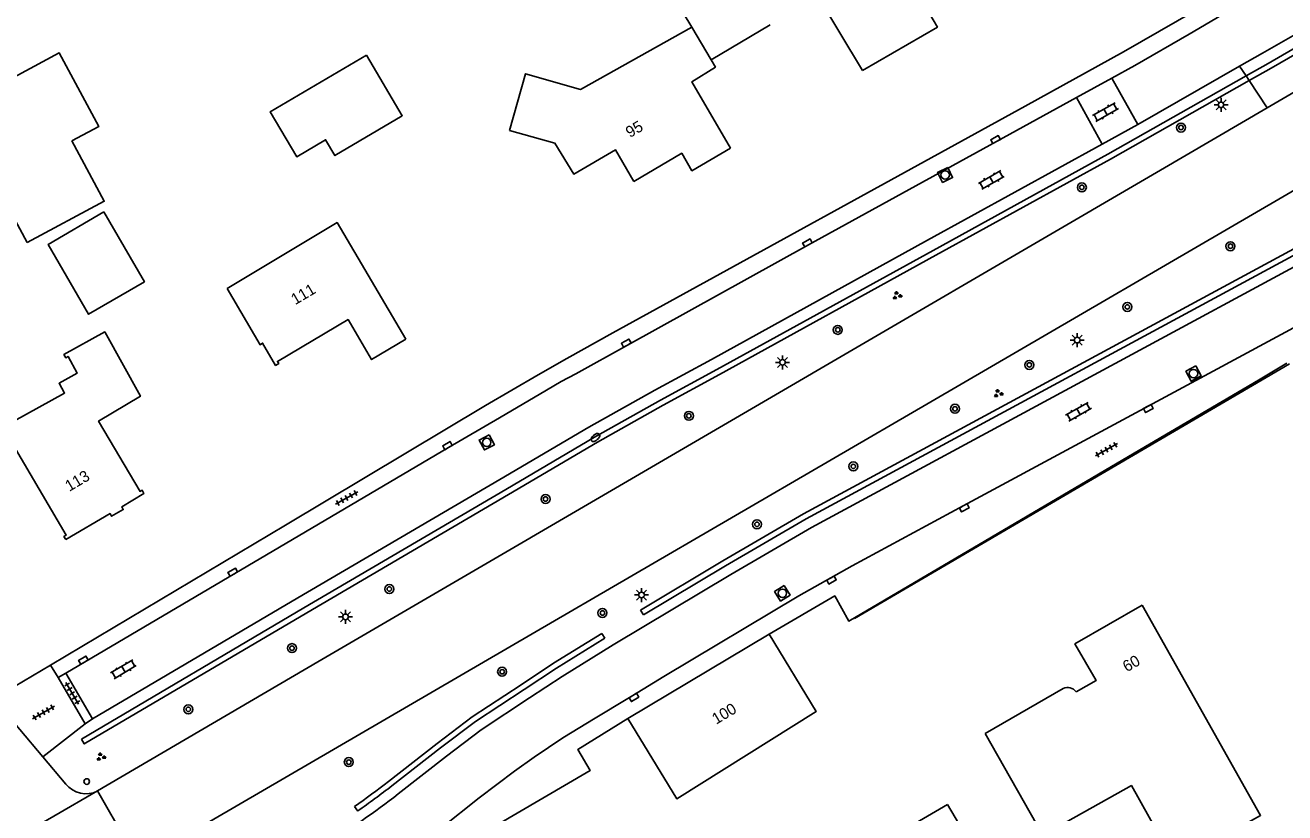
# Model space of a CAD drawing. Extents: x 135999 to 138000, y 396000 to 398501.
# Drawn here: x 136302.3 to 136414.4, y 397566.8 to 397636.9 of the extents above; entities that cross this region are included whole.
import ezdxf

# ---------------------------------------------------------------- set-up
doc = ezdxf.new("R2010")
doc.units = 0
for name, color, linetype in [('gg-afsc-hekwerk', 7, 'Continuous'), ('gg-anno-huisnummerreeks BGT', 7, 'Continuous'), ('gg-bbg-bijgebouw', 7, 'Continuous'), ('gg-bbg-gedigitaliseerde bebouwing', 7, 'Continuous'), ('gg-bbg-gedigitaliseerde bijgebouw', 7, 'Continuous'), ('gg-bbg-hoofdgebouw', 7, 'Continuous'), ('gg-bbg-luifel en loopbrug', 7, 'Continuous'), ('gg-knt-verharding', 7, 'Continuous'), ('gt-grn-groengrens', 7, 'Continuous'), ('gt-grn-weggrens', 7, 'Continuous'), ('gt-symb-boom', 7, 'Continuous'), ('gt-symb-brandkraan', 7, 'Continuous'), ('gt-symb-groenvak', 7, 'Continuous'), ('gt-symb-klinker verharding', 7, 'Continuous'), ('gt-symb-kolk', 7, 'Continuous'), ('gt-symb-lichtmast', 7, 'Continuous'), ('gt-symb-rioolschacht', 7, 'Continuous'), ('gt-symb-tegel verharding', 7, 'Continuous'), ('gt-symb-verkeersregelinstallatiepaal', 7, 'Continuous')]:
    doc.layers.add(name, color=color, linetype=linetype)

# ---------------------------------------------------------------- blocks, each defined once
blk = doc.blocks.new('gt0-BOOM')
at = {"layer": 'gt-symb-boom'}
for radius in [0.4, 0.2]:
    blk.add_circle((0, 0), radius, dxfattribs=at)
blk = doc.blocks.new('gt0-GRVAK')
at = {"layer": 'gt-symb-groenvak'}
for p, q in [((-0.11, 0.19), (-0.23, 0.24)), ((-0.18, 0.15), (0.09, 0.15)), ((-0.09, 0.21), (-0.16, 0.32)), ((-0.05, 0.21), (-0.05, 0.39)), ((0, 0.21), (0.06, 0.32)), ((0.02, 0.19), (0.13, 0.24)), ((0.26, -0.05), (0.2, 0.06)), ((0.3, -0.05), (0.3, 0.13)), ((0.35, -0.05), (0.41, 0.06)), ((-0.24, -0.23), (-0.36, -0.18)), ((-0.32, -0.26), (-0.05, -0.26)), ((-0.23, -0.21), (-0.29, -0.1)), ((-0.18, -0.2), (-0.18, -0.02)), ((-0.14, -0.21), (-0.07, -0.1)), ((-0.12, -0.23), (0, -0.18)), ((0.24, -0.07), (0.12, -0.02)), ((0.17, -0.11), (0.44, -0.11)), ((0.37, -0.07), (0.49, -0.02))]:
    blk.add_line(p, q, dxfattribs=at)
blk = doc.blocks.new('gt0-RS')
at = {"layer": 'gt-symb-rioolschacht'}
blk.add_lwpolyline([(-0.5, -0.5), (0.5, -0.5), (0.5, 0.5), (-0.5, 0.5)], close=True, dxfattribs=at)
blk.add_circle((0, 0), 0.375, dxfattribs=at)
blk = doc.blocks.new('gt0-KL1')
at = {"layer": 'gt-symb-klinker verharding'}
for p, q in [((-1.15, 0.3), (1.15, 0.3)), ((-1, -0.3), (-1, 0.3)), ((-0.5, 0.3), (-0.5, 0.45)), ((0, -0.3), (0, 0.3)), ((0.5, 0.3), (0.5, 0.45)), ((1, -0.3), (1, 0.3)), ((-1.15, -0.3), (1.15, -0.3)), ((-0.5, -0.45), (-0.5, -0.3)), ((0.5, -0.45), (0.5, -0.3))]:
    blk.add_line(p, q, dxfattribs=at)
blk = doc.blocks.new('gt0-KOLK')
at = {"layer": 'gt-symb-kolk'}
blk.add_lwpolyline([(0, 0), (0.38, 0), (0.38, 0.4), (-0.38, 0.4), (-0.38, 0), (0, 0)], dxfattribs=at)
blk = doc.blocks.new('gt0-LMAST')
at = {"layer": 'gt-symb-lichtmast'}
for p, q in [((-0.18, 0.17), (-0.45, 0.44)), ((-0.01, 0.25), (-0.01, 0.62)), ((0.17, 0.17), (0.44, 0.44)), ((-0.26, 0), (-0.63, 0)), ((-0.18, -0.18), (-0.45, -0.45)), ((-0.01, -0.25), (-0.01, -0.63)), ((0.44, -0.45), (0.17, -0.18)), ((0.24, 0), (0.62, 0))]:
    blk.add_line(p, q, dxfattribs=at)
blk.add_circle((-0.01, 0), 0.25, dxfattribs=at)
blk = doc.blocks.new('gt0-TEG1')
at = {"layer": 'gt-symb-tegel verharding'}
for p, q in [((-1.12, 0), (1.13, 0)), ((-0.9, -0.25), (-0.9, 0.25)), ((-0.45, -0.25), (-0.45, 0.25)), ((0, -0.25), (0, 0.25)), ((0.45, -0.25), (0.45, 0.25)), ((0.9, -0.25), (0.9, 0.25))]:
    blk.add_line(p, q, dxfattribs=at)
blk = doc.blocks.new('gt0-BR')
at = {"layer": 'gt-symb-brandkraan'}
for centre, radius, start, end in [((-0.24, 0), 0.206, 107.5669, 252.4331), ((0.6, -2.66), 3, 106.892, 107.5669), ((0, -0.69), 0.938, 73.108, 106.892), ((-0.6, -2.66), 3, 72.4331, 73.108), ((0.24, 0), 0.206, 287.567, 72.4331), ((0.6, 2.66), 3, 252.4331, 253.108), ((0, 0.69), 0.938, 253.108, 286.8921), ((-0.6, 2.66), 3, 286.8921, 287.567)]:
    blk.add_arc(centre, radius, start, end, dxfattribs=at)
blk = doc.blocks.new('gt0-VIPAAL')
at = {"layer": 'gt-symb-verkeersregelinstallatiepaal'}
blk.add_circle((0, 0), 0.25, dxfattribs=at)

msp = doc.modelspace()

# ---------------------------------------------------------------- linework, layer by layer
at = {"layer": 'gg-afsc-hekwerk'}
msp.add_line((136414.81, 397606.76), (136376.12, 397584.09), dxfattribs=at)
at = {"layer": 'gg-bbg-bijgebouw'}
msp.add_lwpolyline([(136293.54, 397628.05), (136297.09, 397621.4), (136299.69, 397622.8), (136302.52, 397617.53)], dxfattribs=at)
at = {"layer": 'gg-bbg-gedigitaliseerde bebouwing'}
msp.add_line((136371.92, 397641.05), (136376.85, 397632.84), dxfattribs=at)
for points in [[(136345.43, 397627.52), (136346.86, 397632.55), (136351.76, 397631.16), (136361.66, 397636.71)], [(136336.22, 397608.94), (136330.09, 397619.32), (136320.31, 397613.45)], [(136387.75, 397573.87), (136392.87, 397564.81), (136400.76, 397569.22), (136404.63, 397562.31), (136412.25, 397566.57), (136401.72, 397585.27)], [(136368.53, 397582.68), (136372.71, 397575.8), (136360.31, 397568.05), (136355.96, 397575.19)]]:
    msp.add_lwpolyline(points, dxfattribs=at)
at = {"layer": 'gg-bbg-gedigitaliseerde bijgebouw'}
for points in [[(136306.5, 397626.58), (136308.89, 397627.86), (136305.36, 397634.42), (136293.54, 397628.05)], [(136332.7, 397634.22), (136335.89, 397628.82), (136329.9, 397625.28), (136329.07, 397626.69), (136326.5, 397625.17), (136324.14, 397629.16), (136332.7, 397634.22)], [(136306.5, 397626.58), (136309.38, 397621.21), (136302.52, 397617.53)], [(136309.35, 397620.26), (136304.38, 397617.36), (136307.99, 397611.16), (136312.96, 397614.05), (136309.35, 397620.26)], [(136384.39, 397567.55), (136379.42, 397564.62), (136385.01, 397555.15), (136389.98, 397558.09), (136384.39, 397567.55)]]:
    msp.add_lwpolyline(points, dxfattribs=at)
at = {"layer": 'gg-bbg-hoofdgebouw'}
for p, q in [((136363.37, 397633.79), (136361.66, 397636.71)), ((136368.53, 397582.68), (136355.96, 397575.19)), ((136387.75, 397573.87), (136394.7, 397577.85))]:
    msp.add_line(p, q, dxfattribs=at)
for points in [[(136376.85, 397632.84), (136383.5, 397636.71), (136382.74, 397638.02)], [(136365.08, 397625.94), (136361.65, 397631.83), (136363.75, 397633.15), (136363.37, 397633.79)], [(136356.49, 397622.98), (136354.85, 397625.79), (136351.15, 397623.63), (136349.48, 397626.38), (136345.43, 397627.52)], [(136365.08, 397625.94), (136361.66, 397623.93), (136360.76, 397625.48), (136356.49, 397622.98)], [(136320.31, 397613.45), (136323.24, 397608.44), (136323.47, 397608.6), (136324.63, 397606.61), (136324.91, 397606.78), (136324.79, 397606.96), (136331.08, 397610.68), (136333.17, 397607.13), (136336.22, 397608.94)], [(136305.96, 397591.11), (136305.79, 397591.38), (136305.99, 397591.5), (136300.69, 397600.54), (136300.48, 397600.45), (136300.22, 397601.01), (136305.85, 397604.14), (136305.36, 397605.02), (136306.98, 397605.92), (136306.16, 397607.4), (136305.96, 397607.29), (136305.8, 397607.57), (136309.43, 397609.58), (136312.6, 397603.86), (136308.88, 397601.66), (136312.57, 397595.39), (136312.76, 397595.5), (136312.91, 397595.22), (136310.94, 397594.01), (136311.07, 397593.78), (136310.04, 397593.19), (136309.9, 397593.43), (136305.96, 397591.11)], [(136395.84, 397577.57), (136397.61, 397578.57), (136395.74, 397581.82), (136401.72, 397585.27)]]:
    msp.add_lwpolyline(points, dxfattribs=at)
msp.add_arc((136395.11, 397577.06), 0.888, 34.8378, 117.5399, dxfattribs=at)
at = {"layer": 'gg-bbg-luifel en loopbrug'}
for p, q in [((136360.21, 397639.11), (136361.66, 397636.71)), ((136363.37, 397633.79), (136368.62, 397636.9))]:
    msp.add_line(p, q, dxfattribs=at)
at = {"layer": 'gg-knt-verharding'}
for p, q in [((136410.39, 397633.23), (136401.33, 397628.04)), ((136395.86, 397630.43), (136399.03, 397632.17)), ((136401.33, 397628.04), (136399.03, 397632.17)), ((136398.16, 397626.3), (136395.86, 397630.43)), ((136401.33, 397628.04), (136398.16, 397626.3)), ((136301.39, 397578.04), (136304.6, 397579.95)), ((136305.97, 397579.23), (136305.27, 397578.83)), ((136308.35, 397575.16), (136305.97, 397579.23)), ((136305.27, 397578.83), (136307.68, 397574.73)), ((136299.55, 397576.95), (136303.92, 397571.77)), ((136307.68, 397574.73), (136308.35, 397575.16)), ((136303.92, 397571.77), (136307.68, 397574.73)), ((136303.92, 397571.77), (136305.95, 397569.36))]:
    msp.add_line(p, q, dxfattribs=at)
for points in [[(136579.49, 397726.69), (136481.87, 397669.84), (136412.85, 397629.52)], [(136304.6, 397579.95), (136325.51, 397592.38), (136343.3, 397603.04), (136347.99, 397605.78), (136350.54, 397607.23), (136354.63, 397609.5), (136391.3, 397629.68), (136400.05, 397634.52), (136406.45, 397638.18), (136406.68, 397637.81), (136417.89, 397644.3), (136433.25, 397653.2), (136433.03, 397653.57), (136437.76, 397656.34), (136532.96, 397711.6), (136538.18, 397714.81), (136538.26, 397714.66), (136539.91, 397715.62), (136551.96, 397722.69)], [(136482.6, 397674.13), (136434.79, 397646.42), (136429.31, 397643.24), (136423.93, 397640.21), (136420.97, 397638.93), (136418.41, 397637.78), (136415.53, 397636.18), (136412.41, 397634.38), (136410.39, 397633.23)], [(136399.03, 397632.17), (136401.05, 397633.29), (136405.89, 397636.07), (136409.79, 397638.35), (136414.32, 397640.95)], [(136454.41, 397631.76), (136442.38, 397624.71), (136424.64, 397615.04), (136407.64, 397605.89), (136385.8, 397594.1), (136375.91, 397588.77), (136371.17, 397586.09), (136359.16, 397578.94), (136356.4, 397577.24), (136355.96, 397576.96), (136353.05, 397575.22), (136350.19, 397573.46), (136347.62, 397571.75), (136345.87, 397570.5), (136342.75, 397568.12), (136339.37, 397565.46), (136337.59, 397564.11), (136335.32, 397562.48), (136333.1, 397561.03), (136330.86, 397559.61), (136325.73, 397556.55), (136319.82, 397553.1)], [(136395.86, 397630.43), (136388.77, 397626.52), (136372.04, 397617.33), (136355.92, 397608.42), (136351.33, 397605.86), (136350.03, 397605.16), (136348.72, 397604.4), (136344.53, 397601.93), (136340.02, 397599.3), (136305.97, 397579.23)], [(136412.85, 397629.52), (136403.35, 397623.97), (136366.25, 397602.33), (136328.37, 397580.22), (136308.79, 397568.74)], [(136398.16, 397626.3), (136382.61, 397617.76), (136363.39, 397607.14), (136358.36, 397604.41), (136352.48, 397601.11), (136344.57, 397596.46), (136326.61, 397585.93), (136308.35, 397575.16)], [(136416.94, 397623.19), (136382.92, 397603.38), (136347.46, 397582.71), (136312.47, 397562.36)], [(136420.4, 397618.17), (136372.29, 397592.18), (136365.13, 397588), (136354.67, 397581.74), (136350.11, 397578.92), (136347.22, 397577.03), (136342.92, 397574.18), (136339.84, 397571.85), (136335.52, 397568.48)], [(136368.53, 397582.68), (136374.37, 397586.1), (136375.62, 397583.86), (136400.99, 397598.79), (136412.08, 397605.29), (136414.59, 397606.81)], [(136314.37, 397548.1), (136331.52, 397558.36), (136331.57, 397558.27), (136352.62, 397570.57), (136351.5, 397572.43), (136355.96, 397575.19)]]:
    msp.add_lwpolyline(points, dxfattribs=at)
for centre, radius, start, end in [((136307.75, 397570.78), 2.29, 218.3217, 297.2056), ((136281.03, 397639.28), 89.35, 302.4714, 307.5845)]:
    msp.add_arc(centre, radius, start, end, dxfattribs=at)
at = {"layer": 'gt-grn-groengrens'}
for p, q in [((136410.39, 397633.23), (136410.96, 397632.36)), ((136410.96, 397632.36), (136398.66, 397625.39)), ((136411.24, 397631.95), (136398.9, 397624.96)), ((136410.96, 397632.36), (136411.24, 397631.95)), ((136411.24, 397631.95), (136412.85, 397629.52)), ((136357.34, 397584.4), (136357.08, 397584.83)), ((136353.65, 397582.76), (136353.92, 397582.34)), ((136331.94, 397566.96), (136331.65, 397567.36))]:
    msp.add_line(p, q, dxfattribs=at)
for points in [[(136418.87, 397636.85), (136416.04, 397635.28), (136412.93, 397633.48), (136410.96, 397632.36)], [(136419.12, 397636.42), (136416.29, 397634.84), (136413.18, 397633.05), (136411.24, 397631.95)], [(136398.66, 397625.39), (136383.11, 397616.84), (136363.89, 397606.23), (136358.87, 397603.5), (136353, 397600.21), (136345.1, 397595.56), (136327.14, 397585.03), (136307.35, 397573.36)], [(136398.9, 397624.96), (136383.35, 397616.41), (136364.12, 397605.79), (136359.11, 397603.06), (136353.25, 397599.77), (136345.35, 397595.13), (136327.39, 397584.6), (136307.6, 397572.93), (136307.35, 397573.36)], [(136419.61, 397619.35), (136371.59, 397593.41), (136364.41, 397589.21), (136357.08, 397584.83)], [(136419.89, 397618.93), (136371.84, 397592.97), (136364.66, 397588.78), (136357.34, 397584.4)], [(136353.65, 397582.76), (136349.35, 397580.1), (136346.46, 397578.2), (136342.11, 397575.33), (136338.99, 397572.96), (136334.67, 397569.59)], [(136353.92, 397582.34), (136349.62, 397579.68), (136346.73, 397577.78), (136342.4, 397574.92), (136339.29, 397572.57), (136334.98, 397569.19)]]:
    msp.add_lwpolyline(points, dxfattribs=at)
for centre, radius, start, end in [((136280.56, 397639.93), 88.75, 305.1459, 307.5671), ((136280.53, 397639.96), 89.28, 305.1523, 307.5727)]:
    msp.add_arc(centre, radius, start, end, dxfattribs=at)
at = {"layer": 'gt-grn-weggrens'}
for p, q in [((136305.27, 397578.83), (136304.6, 397579.95)), ((136295.87, 397561.3), (136308.79, 397568.74)), ((136308.79, 397568.74), (136312.47, 397562.36))]:
    msp.add_line(p, q, dxfattribs=at)

# ---------------------------------------------------------------- block references
at = {"layer": 'gt-symb-boom'}
for p in [(136405.17, 397627.77), (136396.35, 397622.45), (136409.57, 397617.21), (136400.4, 397611.81), (136374.64, 397609.77), (136391.68, 397606.65), (136385.06, 397602.75), (136361.39, 397602.12), (136376.02, 397597.62), (136348.64, 397594.72), (136367.45, 397592.47), (136334.75, 397586.71), (136353.7, 397584.58), (136326.09, 397581.45), (136344.78, 397579.35), (136316.86, 397576), (136331.14, 397571.31)]:
    msp.add_blockref('gt0-BOOM', p, dxfattribs=at)
at = {"layer": 'gt-symb-brandkraan', "rotation": -137.83811877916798}
msp.add_blockref('gt0-BR', (136353.08, 397600.19), dxfattribs=at)
at = {"layer": 'gt-symb-groenvak'}
for p in [(136379.9, 397612.82), (136388.9, 397604.11), (136309.07, 397571.77)]:
    msp.add_blockref('gt0-GRVAK', p, dxfattribs=at)
at = {"layer": 'gt-symb-klinker verharding'}
for p, rotation in [((136398.45, 397629.15), 29.538782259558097), ((136388.3, 397623.11), 29.66671520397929), ((136396.05, 397602.49), 29.666715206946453), ((136311.09, 397579.57), 30.541098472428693)]:
    msp.add_blockref('gt0-KL1', p, dxfattribs=dict(at, rotation=rotation))
at = {"layer": 'gt-symb-kolk'}
for p, rotation in [((136388.77, 397626.52), 28.743035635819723), ((136372.04, 397617.33), 28.94886164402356), ((136355.92, 397608.42), 29.126912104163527), ((136402.17, 397602.94), -151.64103655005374), ((136340.02, 397599.3), 30.541098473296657), ((136385.8, 397594.1), -151.64103655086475), ((136320.92, 397588.04), 30.462640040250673), ((136373.98, 397587.68), -150.46121774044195), ((136307.63, 397580.21), 30.59043540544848), ((136356.4, 397577.24), -148.40750843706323)]:
    msp.add_blockref('gt0-KOLK', p, dxfattribs=dict(at, rotation=rotation))
at = {"layer": 'gt-symb-lichtmast'}
for p in [(136408.74, 397629.79), (136395.95, 397608.86), (136369.73, 397606.88), (136357.19, 397586.18), (136330.86, 397584.23)]:
    msp.add_blockref('gt0-LMAST', p, dxfattribs=at)
at = {"layer": 'gt-symb-rioolschacht'}
for p, rotation in [((136384.19, 397623.55), -154.15238978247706), ((136406.28, 397605.88), -151.81960518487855), ((136343.41, 397599.76), -152.10272896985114), ((136369.71, 397586.33), -147.7881026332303)]:
    msp.add_blockref('gt0-RS', p, dxfattribs=dict(at, rotation=rotation))
at = {"layer": 'gt-symb-tegel verharding'}
for p, rotation in [((136398.54, 397599.1), 28.998977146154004), ((136330.94, 397594.81), 28.998977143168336), ((136306.53, 397577.43), -59.949676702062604), ((136303.97, 397575.73), 29.87282104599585)]:
    msp.add_blockref('gt0-TEG1', p, dxfattribs=dict(at, rotation=rotation))
at = {"layer": 'gt-symb-verkeersregelinstallatiepaal', "rotation": 119.9811016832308}
msp.add_blockref('gt0-VIPAAL', (136307.82, 397569.58), dxfattribs=at)

# ---------------------------------------------------------------- texts
at = {"layer": 'gg-anno-huisnummerreeks BGT'}
for s, rotation, p in [('95', 30.3, (136356.14, 397626.83)), ('111', 30.6, (136326.37, 397611.96)), ('113', 30.5, (136306.27, 397595.35)), ('60', 29.9, (136400.35, 397579.29)), ('100', 30.8, (136363.82, 397574.63))]:
    msp.add_text(s, height=1, rotation=rotation, dxfattribs=at).set_placement(p)

doc.saveas('drawing.dxf')
